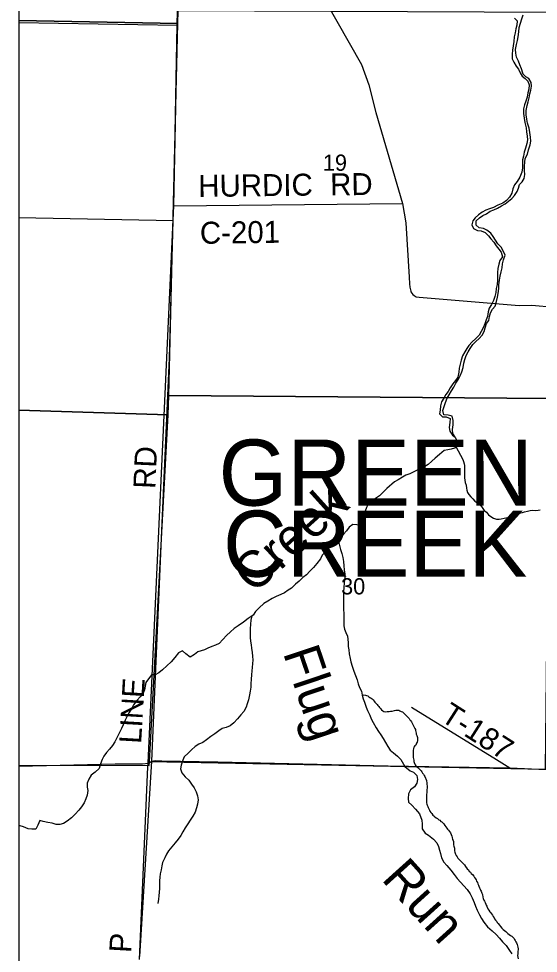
# Model space of a CAD drawing. Extents: x 0 to 34, y 0 to 22.
# Drawn here: x 2.1 to 3.441, y 15.033 to 17.445 of the extents above; entities that cross this region are included whole.
import ezdxf

# ---------------------------------------------------------------- set-up
doc = ezdxf.new("R2010")
doc.units = 0
for name, color, linetype in [('Default', 7, 'Continuous'), ('GM_X_County_Road', 7, 'Continuous'), ('GM_X_County_Road_Text', 7, 'Continuous'), ('GM_X_Minor_River', 7, 'Continuous'), ('GM_X_Minor_River_Text', 7, 'Continuous'), ('GM_X_Section', 7, 'Continuous'), ('GM_X_Section_Text', 7, 'Continuous'), ('GM_X_Township', 7, 'Continuous'), ('GM_X_Township_Road', 7, 'Continuous'), ('GM_X_Township_Road_Text', 7, 'Continuous'), ('GM_X_Township_Text', 7, 'Continuous'), ('SH_Cut_Line', 7, 'Continuous'), ('SH_Data', 7, 'Continuous')]:
    doc.layers.add(name, color=color, linetype=linetype)

msp = doc.modelspace()

# ---------------------------------------------------------------- linework, layer by layer
at = {"layer": 'Default'}
for points in [[(2.1, 18.4416), (2.1, 17.4406), (2.5103, 17.4328), (2.5117, 17.4662), (2.54, 18.4332)], [(2.1, 17.4406), (2.1, 16.4346), (2.4859, 16.423), (2.4877, 16.4726), (2.5103, 17.4328)], [(2.1, 16.4346), (2.1, 15.5183), (2.4371, 15.5179), (2.4379, 15.527), (2.4859, 16.423)]]:
    msp.add_lwpolyline(points, close=True, dxfattribs=at)
at = {"layer": 'GM_X_County_Road'}
for p, q in [((2.5095, 17.4283), (2.5258, 18.084)), ((2.5005, 16.962), (2.5095, 17.4283)), ((2.4988, 16.9244), (2.5005, 16.962)), ((2.5005, 16.962), (3.0902, 16.9681)), ((2.1, 16.9318), (2.4988, 16.9244)), ((2.4124, 15.0248), (2.4438, 15.5292))]:
    msp.add_line(p, q, dxfattribs=at)
for points in [[(2.6125, 17.9578), (2.8536, 17.5572), (2.9844, 17.3269), (3.0036, 17.2741), (3.0215, 17.2032), (3.0902, 16.9681)], [(3.0902, 16.9681), (3.0989, 16.9182), (3.1077, 16.7783), (3.1085, 16.7608), (3.1091, 16.7524), (3.1116, 16.7417), (3.1124, 16.7398), (3.1168, 16.7333), (3.1205, 16.7304), (3.1255, 16.7274), (3.1334, 16.7262), (3.3912, 16.7049), (3.4243, 16.7061), (3.4818, 16.701)], [(2.4438, 15.5292), (2.4689, 16.1048), (2.4889, 16.569), (2.4988, 16.9244)], [(2.1, 15.5164), (2.3489, 15.5218), (2.4191, 15.5223), (2.4341, 15.5238), (2.4359, 15.524), (2.4438, 15.5292)], [(2.4438, 15.5292), (2.4519, 15.5304), (2.4695, 15.5303), (2.6138, 15.5274), (3.0538, 15.5169), (3.3677, 15.5116), (3.4615, 15.5078)]]:
    msp.add_lwpolyline(points, dxfattribs=at)
at = {"layer": 'GM_X_Minor_River'}
for points in [[(3.3798, 17.4465), (3.3868, 17.4399), (3.3854, 17.4285), (3.3832, 17.4187), (3.381, 17.4085), (3.3789, 17.3984), (3.3774, 17.3866), (3.376, 17.3753), (3.3741, 17.3635), (3.3735, 17.3537), (3.3739, 17.3419), (3.3778, 17.3327), (3.384, 17.3227), (3.3895, 17.3149), (3.3938, 17.3057), (3.3992, 17.2968), (3.4067, 17.2909)], [(3.401, 17.3043), (3.3975, 17.3158), (3.3932, 17.3262), (3.3897, 17.3358), (3.385, 17.3458), (3.383, 17.3561), (3.3821, 17.366), (3.3851, 17.3784), (3.3869, 17.389), (3.3891, 17.3984), (3.3906, 17.4109), (3.3916, 17.4223), (3.395, 17.4332), (3.3987, 17.4449), (3.4016, 17.4554)], [(3.2265, 16.3648), (3.2207, 16.3745), (3.2195, 16.3848), (3.2209, 16.3969), (3.2212, 16.4079), (3.2185, 16.419), (3.2087, 16.4219), (3.1974, 16.4226), (3.195, 16.4337), (3.198, 16.4446), (3.2013, 16.4547), (3.2061, 16.466), (3.2113, 16.4746), (3.2172, 16.4843), (3.2228, 16.494), (3.2284, 16.5041), (3.2351, 16.5146), (3.2395, 16.5232), (3.2432, 16.5341), (3.2469, 16.5446), (3.2491, 16.5563), (3.2513, 16.5658), (3.255, 16.5755), (3.2602, 16.5853), (3.2653, 16.5939), (3.272, 16.6039), (3.2798, 16.6117), (3.2884, 16.6194), (3.2962, 16.6283), (3.3014, 16.638), (3.3039, 16.6475), (3.3069, 16.6584), (3.3132, 16.6666), (3.315, 16.6768), (3.3175, 16.6862), (3.3227, 16.6956), (3.3297, 16.7033), (3.3331, 16.715), (3.3356, 16.7263), (3.3374, 16.7362), (3.3389, 16.7486), (3.3395, 16.7585), (3.341, 16.7699), (3.3428, 16.7808), (3.3454, 16.7918), (3.3476, 16.8023), (3.3482, 16.8126), (3.3515, 16.8227), (3.3553, 16.8348), (3.3506, 16.8459), (3.3448, 16.8556), (3.3367, 16.8645), (3.3305, 16.8738), (3.3243, 16.8831), (3.3181, 16.892), (3.3085, 16.8995), (3.2991, 16.9039), (3.2882, 16.9053), (3.2804, 16.912), (3.2807, 16.9238), (3.2888, 16.9308), (3.2977, 16.937), (3.307, 16.9417), (3.3166, 16.9482), (3.3258, 16.9521), (3.3354, 16.9564), (3.3462, 16.9618), (3.3558, 16.9677), (3.3639, 16.9739), (3.3729, 16.9812), (3.3791, 16.989), (3.3862, 16.9987), (3.3895, 17.0081), (3.3924, 17.0171), (3.3994, 17.0242), (3.4042, 17.0331), (3.406, 17.0433), (3.4052, 17.0536), (3.4055, 17.0642), (3.4061, 17.0752), (3.4068, 17.0847), (3.4127, 17.0956), (3.4157, 17.1065), (3.4198, 17.1193), (3.422, 17.1287), (3.4211, 17.139), (3.4188, 17.1512), (3.4176, 17.1623), (3.4134, 17.1757), (3.4114, 17.1856), (3.4098, 17.1966), (3.4093, 17.208), (3.412, 17.2213), (3.4145, 17.2307), (3.4174, 17.2409), (3.4189, 17.2514), (3.4214, 17.2609), (3.4236, 17.2711), (3.4227, 17.2806), (3.4169, 17.2906), (3.4087, 17.2954)], [(3.4087, 17.2954), (3.4017, 17.302), (3.401, 17.3043)], [(3.4067, 17.2909), (3.4141, 17.2842), (3.4172, 17.2747), (3.4165, 17.2629), (3.414, 17.2535), (3.4118, 17.2422), (3.4089, 17.232), (3.4052, 17.223), (3.403, 17.2124), (3.4027, 17.2003), (3.4046, 17.1884), (3.4066, 17.1774), (3.4093, 17.1636), (3.4105, 17.153), (3.4125, 17.1423), (3.4134, 17.1328), (3.4116, 17.1226), (3.4075, 17.1113), (3.4045, 17.1003), (3.4024, 17.0905), (3.4006, 17.0811), (3.3999, 17.0705), (3.4, 17.0606), (3.3986, 17.0489), (3.3937, 17.0361), (3.3866, 17.0253), (3.3799, 17.0167), (3.3751, 17.0062), (3.3729, 16.9945), (3.3665, 16.9841), (3.3591, 16.9763), (3.349, 16.969), (3.3368, 16.964), (3.3256, 16.9575), (3.3153, 16.9543), (3.3057, 16.9508), (3.2957, 16.9458), (3.2864, 16.9388), (3.2782, 16.9314), (3.272, 16.9233), (3.2698, 16.9127), (3.2733, 16.9035), (3.2842, 16.8986), (3.2936, 16.8972), (3.3037, 16.8931), (3.3126, 16.8845), (3.3181, 16.8768), (3.3258, 16.8682), (3.3324, 16.8586), (3.3394, 16.8504), (3.3449, 16.8427), (3.3487, 16.8304), (3.342, 16.8207), (3.3387, 16.8117), (3.3369, 16.8), (3.3355, 16.7905), (3.336, 16.7806), (3.3353, 16.77), (3.3346, 16.759), (3.3324, 16.7484), (3.331, 16.7382), (3.3292, 16.7284), (3.3255, 16.7175), (3.3203, 16.7074), (3.314, 16.6977), (3.3119, 16.6883), (3.3097, 16.6769), (3.3064, 16.6679), (3.3027, 16.6578), (3.2986, 16.6472), (3.2938, 16.6379), (3.2886, 16.6281), (3.2793, 16.6189), (3.27, 16.6112), (3.2621, 16.6019), (3.2562, 16.5941), (3.2514, 16.5855), (3.2455, 16.5747), (3.2421, 16.5641), (3.2396, 16.5532), (3.2366, 16.543), (3.236, 16.5331), (3.233, 16.5203), (3.2275, 16.5117), (3.22, 16.5024), (3.2133, 16.4928), (3.2081, 16.4834), (3.2026, 16.4752), (3.197, 16.4655), (3.1911, 16.4562), (3.1889, 16.4463), (3.1875, 16.435), (3.1864, 16.4252), (3.1934, 16.4177), (3.2029, 16.4175), (3.2134, 16.4134), (3.2128, 16.4028), (3.2113, 16.3903), (3.2129, 16.3808), (3.2191, 16.3707), (3.2265, 16.3648)], [(3.2265, 16.3648), (3.2304, 16.356), (3.2286, 16.3439), (3.2281, 16.3412), (3.2246, 16.3366)], [(3.2246, 16.3366), (3.216, 16.3342), (3.2072, 16.3324), (3.1981, 16.3309), (3.1862, 16.3208), (3.1751, 16.3107), (3.1659, 16.3028), (3.1571, 16.2949), (3.1479, 16.2894), (3.1392, 16.2864), (3.1178, 16.2745), (3.109, 16.2704), (3.0995, 16.2675), (3.0904, 16.2619), (3.0793, 16.2552), (3.0697, 16.25), (3.0498, 16.2327), (3.0406, 16.2233), (3.031, 16.2139), (3.018, 16.205), (3.0092, 16.2013), (3.0019, 16.1922), (2.998, 16.1835), (2.9938, 16.1745), (2.9914, 16.1643), (2.9912, 16.1445), (2.9816, 16.1378), (2.9729, 16.139), (2.9623, 16.1395), (2.9531, 16.1328), (2.9458, 16.1237), (2.9381, 16.1147), (2.93, 16.1046), (2.9208, 16.0974), (2.9101, 16.0896), (2.9002, 16.0806), (2.8932, 16.0716), (2.8836, 16.0606), (2.879, 16.0512), (2.8693, 16.0388), (2.8609, 16.029), (2.8517, 16.0196), (2.8424, 16.0098), (2.8333, 16.0027), (2.8237, 15.9933), (2.8145, 15.9855), (2.8037, 15.9753), (2.795, 15.9701), (2.7862, 15.9638), (2.7762, 15.9589), (2.7648, 15.9541), (2.7545, 15.9489), (2.7427, 15.9422), (2.7327, 15.9355), (2.7209, 15.925), (2.7113, 15.9156), (2.7055, 15.9062), (2.6921, 15.8976), (2.6798, 15.8875), (2.6661, 15.8785), (2.6561, 15.871), (2.6466, 15.8628), (2.6362, 15.853), (2.6266, 15.8433)], [(3.2281, 16.3412), (3.2464, 16.3073), (3.2478, 16.3023), (3.2497, 16.2962), (3.2504, 16.2917), (3.2501, 16.2658), (3.2504, 16.2602), (3.2511, 16.2541), (3.2525, 16.2484), (3.2544, 16.2411), (3.2558, 16.2335), (3.2569, 16.2282), (3.2583, 16.2225), (3.2621, 16.2171), (3.2665, 16.2114), (3.2718, 16.2056), (3.2774, 16.2003), (3.2819, 16.1968), (3.2868, 16.1937), (3.2925, 16.1891), (3.2962, 16.1834), (3.3014, 16.1761), (3.3074, 16.1715), (3.3127, 16.1646), (3.3183, 16.16), (3.3255, 16.1561), (3.3334, 16.1537), (3.3398, 16.1533), (3.3455, 16.1547), (3.3531, 16.1558), (3.3615, 16.1576), (3.3684, 16.1594), (3.3737, 16.162), (3.379, 16.1642), (3.3844, 16.1657), (3.3927, 16.1694), (3.4, 16.1705), (3.4057, 16.1727), (3.4129, 16.1745), (3.4201, 16.1759), (3.427, 16.177), (3.4345, 16.1758), (3.4406, 16.1769), (3.4459, 16.1779)], [(2.9269, 16.1021), (2.9246, 16.0982), (2.9268, 16.089), (2.9308, 16.0753), (2.9341, 16.065), (2.9363, 16.0544), (2.938, 16.0441), (2.9394, 16.0335), (2.9401, 16.0228), (2.9415, 16.0114), (2.9414, 16.0027), (2.9401, 15.9898), (2.9388, 15.9765), (2.9379, 15.9667), (2.9378, 15.953), (2.938, 15.9424), (2.9383, 15.9314), (2.9382, 15.9204), (2.9388, 15.9105), (2.9394, 15.8983), (2.9393, 15.8888), (2.9388, 15.8782), (2.941, 15.8695), (2.9439, 15.8607), (2.9484, 15.8512), (2.9501, 15.8352), (2.9507, 15.8253), (2.9518, 15.8162), (2.9532, 15.8063), (2.9553, 15.7941), (2.9575, 15.785), (2.9608, 15.7743), (2.9648, 15.7614), (2.9692, 15.75), (2.9733, 15.7393), (2.9762, 15.7286), (2.9791, 15.7191), (2.9843, 15.7099), (2.9865, 15.6997), (2.989, 15.6898), (2.9923, 15.681), (2.9971, 15.6688), (3.0001, 15.66), (3.006, 15.6478), (3.01, 15.6379), (3.0145, 15.6284), (3.0223, 15.615), (3.0283, 15.6054), (3.0342, 15.5966), (3.0402, 15.5871), (3.0465, 15.5775), (3.0529, 15.5672), (3.0584, 15.5577), (3.0675, 15.5507), (3.0772, 15.5415), (3.0859, 15.5334), (3.0967, 15.5155), (3.1106, 15.5043), (3.1192, 15.5004), (3.1279, 15.492), (3.1296, 15.4817), (3.1276, 15.4723), (3.1215, 15.4625), (3.1111, 15.455), (3.1057, 15.4448), (3.1048, 15.433), (3.1062, 15.4231), (3.1149, 15.4151), (3.1242, 15.4051), (3.134, 15.3932), (3.1402, 15.3768), (3.1409, 15.3662), (3.1411, 15.3541), (3.1489, 15.343), (3.1576, 15.3383), (3.1704, 15.3275), (3.179, 15.318), (3.1831, 15.3084), (3.1864, 15.2997), (3.1885, 15.2905), (3.1915, 15.2799), (3.197, 15.2688), (3.2049, 15.26), (3.2154, 15.2481), (3.2236, 15.2362), (3.2318, 15.2259), (3.2401, 15.2171), (3.249, 15.2071), (3.2577, 15.1975), (3.2651, 15.1864), (3.2703, 15.1765), (3.2755, 15.1647), (3.2788, 15.1552), (3.2828, 15.1441), (3.2888, 15.1323), (3.2944, 15.1227), (3.3003, 15.1135), (3.3101, 15.1017), (3.3217, 15.0909), (3.3318, 15.0813), (3.3404, 15.0721)], [(2.7019, 15.9039), (2.6993, 15.8933), (2.698, 15.8823), (2.6975, 15.8702), (2.6973, 15.8584), (2.6976, 15.8478), (2.6986, 15.8391), (2.7001, 15.8296), (2.7011, 15.8208), (2.7025, 15.8098), (2.7035, 15.8003), (2.7042, 15.7896), (2.7037, 15.7809), (2.7028, 15.7707), (2.7019, 15.762), (2.7011, 15.7517), (2.7002, 15.7407), (2.6993, 15.7286), (2.6988, 15.7199), (2.6976, 15.7096), (2.6956, 15.7005), (2.6927, 15.6873), (2.69, 15.6767), (2.6872, 15.668), (2.6806, 15.657), (2.6733, 15.6484), (2.6649, 15.6386), (2.6553, 15.6281), (2.6461, 15.6198), (2.6354, 15.6161), (2.6252, 15.6136), (2.6164, 15.6072), (2.606, 15.5998), (2.5957, 15.5927), (2.585, 15.5844), (2.5751, 15.5773), (2.5651, 15.5725), (2.5556, 15.5669), (2.546, 15.5579), (2.5376, 15.5493), (2.5272, 15.5399), (2.5237, 15.5312), (2.519, 15.5191), (2.5174, 15.5096), (2.5211, 15.4993), (2.53, 15.489), (2.5394, 15.4798), (2.5461, 15.4694), (2.5532, 15.4603), (2.5584, 15.4503), (2.5617, 15.4397), (2.5631, 15.429), (2.5615, 15.418), (2.5591, 15.4082), (2.5556, 15.3972), (2.549, 15.387), (2.5424, 15.3765), (2.5366, 15.3674), (2.5293, 15.3573), (2.5235, 15.3463), (2.5185, 15.3373), (2.5115, 15.3275), (2.5038, 15.3184), (2.4869, 15.2977), (2.4815, 15.2887), (2.4768, 15.2796), (2.4714, 15.2672), (2.469, 15.2585), (2.4674, 15.2482), (2.4654, 15.2384), (2.4641, 15.2293), (2.4633, 15.2202), (2.463, 15.2008), (2.4622, 15.1906), (2.4613, 15.1819), (2.4605, 15.1728), (2.4592, 15.1621)], [(2.6266, 15.8433), (2.617, 15.8331), (2.6075, 15.8287), (2.5983, 15.825), (2.5884, 15.8205), (2.5797, 15.8164), (2.5709, 15.8139), (2.5622, 15.8109), (2.5534, 15.8046), (2.5423, 15.7971), (2.5317, 15.8056), (2.5231, 15.814), (2.5128, 15.8088), (2.5032, 15.7968), (2.4932, 15.7855), (2.4825, 15.775), (2.4713, 15.7645), (2.4614, 15.757), (2.4526, 15.7521), (2.4428, 15.7515), (2.4281, 15.7319), (2.4265, 15.7228), (2.4245, 15.7133), (2.4214, 15.7046), (2.4137, 15.6952), (2.4056, 15.6862), (2.396, 15.6745), (2.3917, 15.6659), (2.3855, 15.6545), (2.3801, 15.6455), (2.375, 15.6349), (2.37, 15.6232), (2.3657, 15.6134), (2.3607, 15.6047), (2.3521, 15.5873), (2.3482, 15.5786), (2.3417, 15.5692), (2.3344, 15.5602), (2.3263, 15.5515), (2.3201, 15.5417), (2.3155, 15.5331), (2.3112, 15.5221), (2.3076, 15.5104), (2.2977, 15.5006), (2.287, 15.4927), (2.2808, 15.4822), (2.2765, 15.472), (2.2764, 15.4621), (2.2782, 15.4534), (2.2769, 15.4416), (2.2737, 15.4318), (2.2687, 15.4212), (2.2625, 15.411), (2.2556, 15.4024), (2.246, 15.3926), (2.236, 15.3832), (2.2253, 15.3738), (2.2157, 15.3679), (2.2062, 15.3653), (2.1968, 15.3658), (2.1862, 15.3693), (2.1748, 15.3706), (2.1631, 15.373), (2.1544, 15.3761), (2.1497, 15.364), (2.1443, 15.3538), (2.1336, 15.3536), (2.1242, 15.3548), (2.1128, 15.3595), (2.1042, 15.3622), (2.1, 15.3635)], [(2.9889, 15.6998), (2.995, 15.6996), (2.9976, 15.6984), (3.0006, 15.6972), (3.004, 15.6953), (3.0066, 15.6937), (3.0092, 15.6918), (3.0122, 15.6898), (3.0148, 15.6875), (3.0174, 15.684), (3.0192, 15.6813), (3.0222, 15.6782), (3.0251, 15.6755), (3.027, 15.6728), (3.0292, 15.6701), (3.031, 15.6674), (3.034, 15.6647), (3.0366, 15.6616), (3.0396, 15.6589), (3.0426, 15.6573), (3.0463, 15.6565), (3.0505, 15.6568), (3.0558, 15.6574), (3.0596, 15.6578), (3.0634, 15.6584), (3.0695, 15.6598), (3.0729, 15.6605), (3.0756, 15.6605), (3.0786, 15.6608), (3.0812, 15.6604), (3.0839, 15.6592), (3.0872, 15.6576), (3.0902, 15.656), (3.0928, 15.654), (3.0962, 15.6506), (3.0991, 15.6479), (3.1025, 15.644), (3.1051, 15.6413), (3.1077, 15.639), (3.1095, 15.6359), (3.1121, 15.6332), (3.1135, 15.6301), (3.1157, 15.6267), (3.1172, 15.624), (3.1227, 15.6136), (3.1237, 15.6106), (3.1244, 15.6079), (3.1251, 15.6048), (3.1258, 15.6014), (3.1261, 15.5988), (3.1276, 15.5953), (3.1283, 15.5926), (3.1294, 15.59), (3.1293, 15.5873), (3.1296, 15.5846), (3.1292, 15.582), (3.1284, 15.5782), (3.1268, 15.5756), (3.1252, 15.5703), (3.1225, 15.5685), (3.1201, 15.5651), (3.1193, 15.5617), (3.1184, 15.5564), (3.1183, 15.5507), (3.1179, 15.5477), (3.1178, 15.5424), (3.1184, 15.5386), (3.1188, 15.5352), (3.1194, 15.5317), (3.1197, 15.5283), (3.1208, 15.5256), (3.123, 15.5195), (3.1248, 15.5168), (3.1274, 15.5145), (3.13, 15.5126), (3.133, 15.5098), (3.1386, 15.504), (3.1404, 15.5014), (3.1422, 15.4979), (3.1448, 15.4952), (3.1466, 15.4921), (3.1477, 15.4894), (3.152, 15.4791), (3.1534, 15.4723), (3.1537, 15.4688), (3.154, 15.465), (3.1539, 15.459), (3.1535, 15.4563), (3.153, 15.4529), (3.1529, 15.4472), (3.1524, 15.4438), (3.1524, 15.4412), (3.152, 15.4249), (3.1524, 15.4218), (3.1534, 15.4184), (3.1541, 15.4157), (3.1556, 15.4123), (3.1567, 15.4096), (3.1603, 15.4027), (3.161, 15.4), (3.1632, 15.3969)], [(3.1632, 15.3969), (3.1658, 15.3939), (3.1691, 15.39), (3.1717, 15.3877), (3.1743, 15.385), (3.1773, 15.383), (3.1807, 15.3807), (3.184, 15.3776), (3.187, 15.3764), (3.1892, 15.3737), (3.1918, 15.3721), (3.1944, 15.3698), (3.197, 15.3671), (3.2, 15.3628), (3.2022, 15.3597), (3.2051, 15.3563), (3.207, 15.3536), (3.2088, 15.3509), (3.2114, 15.3478), (3.2144, 15.3443), (3.2176, 15.3352), (3.2183, 15.3321), (3.2197, 15.3272), (3.2211, 15.3241), (3.2222, 15.3214), (3.2221, 15.3157), (3.2224, 15.3131), (3.2227, 15.31), (3.2238, 15.3073), (3.2245, 15.3047), (3.2244, 15.3013), (3.2247, 15.2978), (3.2258, 15.294), (3.2276, 15.2887), (3.229, 15.2856), (3.2312, 15.2818), (3.2334, 15.2791), (3.2397, 15.2725), (3.2423, 15.2702), (3.2453, 15.2667), (3.2475, 15.264), (3.2505, 15.2613), (3.2527, 15.2574), (3.2578, 15.2513), (3.2604, 15.2486), (3.2626, 15.2447), (3.2656, 15.2424), (3.2678, 15.2389), (3.2712, 15.2362), (3.2745, 15.232), (3.2767, 15.2289), (3.2785, 15.2254), (3.2807, 15.2224), (3.2818, 15.2197), (3.284, 15.2155), (3.285, 15.2124), (3.2865, 15.209), (3.2876, 15.2063), (3.2894, 15.2021), (3.2908, 15.199), (3.2919, 15.1963), (3.2934, 15.1933), (3.2952, 15.1887), (3.2966, 15.1849), (3.298, 15.178), (3.299, 15.1746), (3.3005, 15.1704), (3.3023, 15.1673), (3.3034, 15.1642), (3.3052, 15.1604), (3.3066, 15.1577), (3.3081, 15.155), (3.3092, 15.152), (3.311, 15.1482), (3.3132, 15.1443), (3.3161, 15.1405), (3.3183, 15.1378), (3.3202, 15.1347), (3.3227, 15.1316), (3.3246, 15.1282), (3.3268, 15.1247), (3.3282, 15.122), (3.3308, 15.1189), (3.3338, 15.1155), (3.3352, 15.1128), (3.3378, 15.1097), (3.3404, 15.1062), (3.3433, 15.102), (3.347, 15.0977), (3.3507, 15.0946), (3.3537, 15.0923), (3.3571, 15.0896), (3.3597, 15.0869), (3.3626, 15.0845), (3.366, 15.0814), (3.369, 15.0795), (3.3723, 15.0771), (3.3753, 15.0752), (3.3783, 15.0717), (3.3794, 15.069), (3.3812, 15.0663)], [(3.3404, 15.0721), (3.3487, 15.0629), (3.358, 15.0529), (3.3666, 15.0407), (3.3726, 15.0315)], [(3.3812, 15.0663), (3.383, 15.0629), (3.3845, 15.0602), (3.3863, 15.056), (3.388, 15.0487), (3.3887, 15.0446), (3.389, 15.0419), (3.3882, 15.0385), (3.3877, 15.0355), (3.3877, 15.0317), (3.3872, 15.0271), (3.3886, 15.0192)]]:
    msp.add_lwpolyline(points, dxfattribs=at)
at = {"layer": 'GM_X_Section'}
for points in [[(3.4982, 17.462), (3.4692, 16.4646), (2.4877, 16.4726), (2.5103, 17.4328), (2.5117, 17.4662)], [(3.4692, 16.4646), (3.4584, 15.5077), (2.4379, 15.527), (2.4859, 16.423), (2.4877, 16.4726)]]:
    msp.add_lwpolyline(points, close=True, dxfattribs=at)
at = {"layer": 'GM_X_Township'}
msp.add_lwpolyline([(2.4116, 15.0173), (2.4334, 15.5145), (2.4339, 15.5244), (2.4986, 16.925), (2.5003, 16.9626), (2.5093, 17.4289), (2.5256, 18.0846)], dxfattribs=at)
at = {"layer": 'GM_X_Township_Road'}
msp.add_line((2.1, 17.4356), (2.5095, 17.4283), dxfattribs=at)
for points in [[(2.4116, 15.0173), (2.4334, 15.5145), (2.4339, 15.5244), (2.4986, 16.925), (2.5003, 16.9626), (2.5093, 17.4289), (2.5256, 18.0846), (2.5616, 18.9348), (2.5619, 18.941), (2.5631, 18.9701), (2.6034, 19.9491), (2.6035, 19.9525), (2.6217, 20.3636), (2.1208, 20.3735), (2.1108, 20.3737), (2.1, 20.3739), (2.1, 14.5206)], [(3.1136, 15.6682), (3.3329, 15.5333), (3.3677, 15.5116)]]:
    msp.add_lwpolyline(points, dxfattribs=at)
at = {"layer": 'SH_Cut_Line'}
msp.add_lwpolyline([(8.9, 20.9), (2.1, 20.9), (2.1, 14.5206)], dxfattribs=at)
at = {"layer": 'SH_Data'}
msp.add_line((2.1, 20.9), (2.1, 14.1), dxfattribs=at)

# ---------------------------------------------------------------- texts
at = {"layer": 'GM_X_County_Road_Text'}
for s, height, rotation, p in [('HURDIC', 0.05682, 0.7187, (2.5638, 16.9849)), ('RD', 0.05682, 0.4936, (2.9039, 16.9891)), ('C-201', 0.05682, 0.8264, (2.568, 16.8639)), ('RD', 0.05682, 87.5314, (2.4526, 16.231)), ('LINE', 0.05682, 86.6697, (2.4159, 15.573)), ('P', 0.0568, 86.7578, (2.3903, 15.0334))]:
    msp.add_text(s, height=height, rotation=rotation, dxfattribs=at).set_placement(p)
at = {"layer": 'GM_X_Minor_River_Text'}
for s, height, rotation, p in [('Creek', 0.09474, 41.9879, (2.7063, 15.9585)), ('Flug', 0.09476, 288.5487, (2.7814, 15.8089)), ('Run', 0.09476, 312.0477, (3.0338, 15.2239))]:
    msp.add_text(s, height=height, rotation=rotation, dxfattribs=at).set_placement(p)
at = {"layer": 'GM_X_Section_Text'}
for s, p in [('19', (2.8849, 17.0526)), ('30', (2.932, 15.9593))]:
    msp.add_text(s, height=0.04186, rotation=0, dxfattribs=at).set_placement(p)
at = {"layer": 'GM_X_Township_Road_Text'}
msp.add_text('T-187', height=0.05682, rotation=327.3955, dxfattribs=at).set_placement((3.1855, 15.6354))
at = {"layer": 'GM_X_Township_Text'}
for s, p in [('GREEN', (2.616, 16.1885)), ('CREEK', (2.6273, 16.0051))]:
    msp.add_text(s, height=0.17045, rotation=0, dxfattribs=at).set_placement(p)

doc.saveas('drawing.dxf')
